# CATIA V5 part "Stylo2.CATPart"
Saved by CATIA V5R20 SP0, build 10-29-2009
Part number: Stylo1.1
Bounding box of the stored display mesh (mm): x -5 to 5, y -3.274 to 25, z -5 to 5
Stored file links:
  D:\Dropbox\IAO\IAO_2010\iao\IAO Reviser CAO\Problemes\IAO_2010_1447_melguidj\Catia_1447_melguidj\Stylo2.CATPart
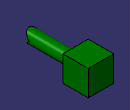
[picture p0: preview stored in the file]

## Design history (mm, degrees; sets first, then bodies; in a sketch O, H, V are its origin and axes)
Body1 (main body)
  Sketch1 on xy-plane, origin (0, 0, 0), H (1, 0, 0), V (0, 1, 0)
    point P1 (0, 15)
    line L1 (0, 15) -> (-2.5, 15)
    line L2 (-2.5, 15) -> (-2.5, -30)
    line L3 (0, -30) -> (0, 15)
    line L4 (0, -30) -> (-2.5, -30)
    distance L2 L3 = 2.5
    distance L1 H = 15
    distance L4 H = 30
    coincidence: P1 V
    horizontal: L1 H, L4 H
    vertical: L2 V, L3 V
  Shaft1: profile Sketch1, axis Sketch1.L3, angle 360
  Sketch2 on xy-plane, origin (0, 0, 0), H (1, 0, 0), V (0, 1, 0)
    point P1 (0, 0)
    point P2 (0, 10)
    distance P2 H = 10
    coincidence: P1 O, P2 V
  Sketch3 on face of Shaft1 from Sketch1.L1, origin (0, 15, 0), H (-1, 0, 0), V (0, 0, 1)
    line L1 (-5, 5) -> (5, 5)
    line L2 (5, 5) -> (5, -5)
    line L3 (5, -5) -> (-5, -5)
    line L4 (-5, -5) -> (-5, 5)
    length L2 = 10
    distance L1 H = 5
    length L1 = 10
    distance L2 V = 5
    horizontal: L1 H, L3 H
    vertical: L2 V, L4 V
  Pad1: profile Sketch3, direction (0, 1, 0), length 10
  Sketch4 on xy-plane, origin (0, 0, 0), H (1, 0, 0), V (0, 1, 0)
    arc A1 centre (0, -0.774) radius 2.5 from (-2.5, -0.774) to (0, -3.274) ccw
    point P1 (0, -0.774)
    point P2 (0, -3.274)
    point P3 (-2.5, -0.774)
    point P4 (-2.5, -0.774)
    line L1 (-2.5, -0.774) -> (-2.5, 3.2781)
    point P5 (-2.5, 3.2781)
    line L2 (-2.5, 3.2781) -> (-6.8161, 3.2781)
    point P6 (-6.8161, 3.2781)
    line L3 (-6.8161, 3.2781) -> (-6.8161, -43.1519)
    point P7 (-6.8161, -43.1519)
    line L4 (-6.8161, -43.1519) -> (0, -43.1519)
    axis line L5 (0, -5.8734) -> (0, -36.7849)
    point P8 (0, -5.8734)
    point P10 (0, -43.1519)
    point P12 (0, -3.274)
    point P13 (2.5, -0.774)
    point P14 (2.5, -0.774)
    point P15 (2.5, 3.2781)
    point P16 (6.8161, 3.2781)
    point P17 (6.8161, -43.1519)
    point P18 (0, -43.1519)
    arc A2 centre (0, -0.774) radius 2.5 from (2.5, -0.774) to (0, -3.274) cw
    line L6 (2.5, -0.774) -> (2.5, 3.2781)
    line L7 (2.5, 3.2781) -> (6.8161, 3.2781)
    line L8 (6.8161, 3.2781) -> (6.8161, -43.1519)
    line L9 (6.8161, -43.1519) -> (0, -43.1519)
    reference projected line E1 (-5, 15) -> (5, 15) from edge [start face of Pad1 | face of Pad1 from Sketch3.L1]
    distance L1 L5 = 2.5
    length L7 = 4.3161
    distance A1 L7 = 6.5521
    distance A1 E1 = 18.274
    coincidence: P1 V, P2 V, P4 A1, P8 V, L5 P10, P3 P4, P2 P12, P10 P18, P13 P14
    vertical: L1 V, L3 V, L5 V
    horizontal: L2 H, L4 H
    tangency: L1 A1
    symmetry: P2 P12 L5, P3 P13 L5, P4 P14 L5, P5 P15 L5, P6 P16 L5, P7 P17 L5, P10 P18 L5, A1 A2 L5, L1 L6 L5, L2 L7 L5, L3 L8 L5, L4 L9 L5
  Pocket1: profile Sketch4, direction (0, 0, -1), length 10, mirrored extent
Body2
  Sketch5 on xy-plane, origin (0, 0, 0), H (1, 0, 0), V (0, 1, 0)
    line L1 (5, 5) -> (5, -5)
    line L2 (5, -5) -> (-5, -5)
    line L3 (-5, -5) -> (-5, 5)
    line L4 (-5, 5) -> (5, 5)
    length L4 = 10
    length L1 = 10
    vertical: L1 V, L3 V
    horizontal: L2 H, L4 H
    equidistance: L1 L3 O, L2 L4 O
  Pad2: profile Sketch5, direction (0, 0, 1), length 10
  Sketch6 on end face of Pad2, origin (0, 0, 10), H (1, 0, 0), V (0, 1, 0)
    circle A1 centre (0, 0) radius 2.5
    point P1 (0, -2.5)
    radius A1 = 2.5
    coincidence: A1 P1, P1 V
  Plane1: type Offset, RefPlane end face of Pad2, Offset 18.274, reversed
  Sketch7 on Plane1, origin (0, 0, 28.274), H (1, 0, 0), V (0, -1, 0)
    circle A1 centre (0, 0) radius 0.1
    radius A1 = 0.1
  Blend1: StartLimit {blendlimit Curve Sketch7, Point {extremum Reference Sketch7, Direction (1, 2, 3)}}, EndLimit {blendlimit Curve Sketch6, Point {extremum Reference Sketch6, Direction (1, 2, 3)}}
  CloseSurface1: CloseElement Blend1
  Pad3: profile Sketch6, direction (0, 0, 1), length 10
  Blend2: StartLimit {blendlimit Curve Sketch7, Point {extremum Reference Sketch7, Direction (1, 2, 3)}}, EndLimit {blendlimit Curve edge [face of Pad3 from Sketch6.A1 | end face of Pad3], Point {extremum Reference edge [face of Pad3 from Sketch6.A1 | end face of Pad3], Direction (1, 2, 3)}}
  CloseSurface2: CloseElement Blend2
